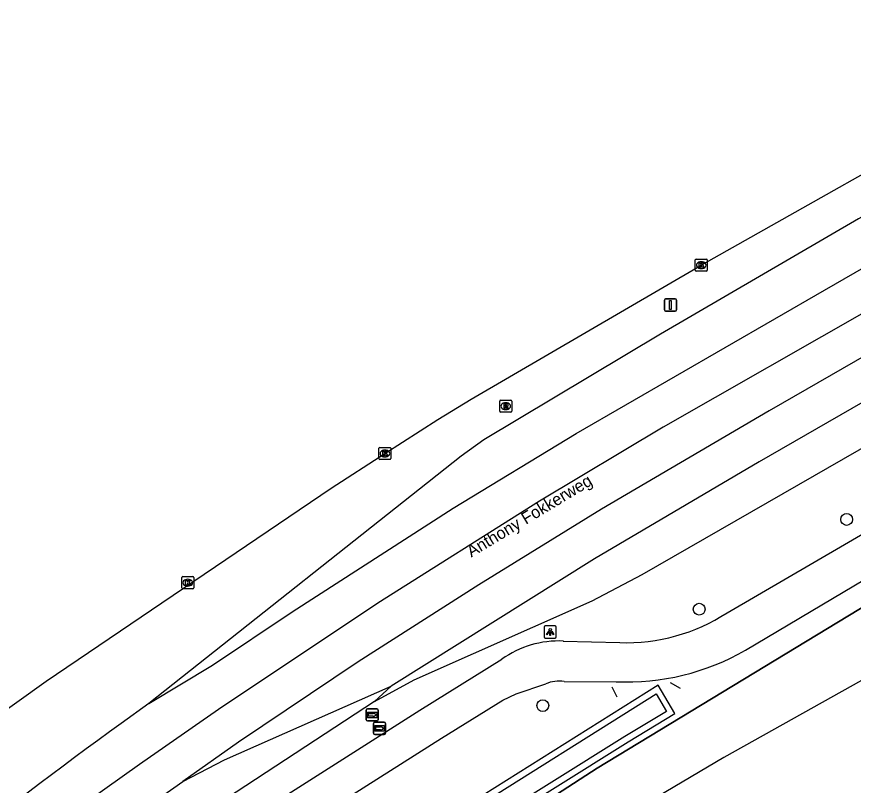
# Model space of a CAD drawing. Extents: x 156502 to 159074, y 384229 to 386094.
# Drawn here: x 157013.2 to 157082.5, y 386020 to 386083.6 of the extents above; entities that cross this region are included whole.
import ezdxf

# ---------------------------------------------------------------- set-up
doc = ezdxf.new("R2010")
doc.units = 0
for name, color, linetype in [('IMGEO_Boom', 7, 'Continuous'), ('IMGEO_Bouwland', 7, 'Continuous'), ('IMGEO_Fietspad_gesloten', 7, 'Continuous'), ('IMGEO_Groenvoorziening', 7, 'Continuous'), ('IMGEO_Hek', 7, 'Continuous'), ('IMGEO_Kolk', 7, 'Continuous'), ('IMGEO_Lichtpunt', 7, 'Continuous'), ('IMGEO_Openbare_ruimte_label', 7, 'Continuous'), ('IMGEO_OVBaan_gesloten', 7, 'Continuous'), ('IMGEO_Rijbaan_regionaal_gesloten', 7, 'Continuous'), ('IMGEO_Rioolput', 7, 'Continuous'), ('IMGEO_Verkeersbordpaal', 7, 'Continuous'), ('IMGEO_Waterloop', 7, 'Continuous'), ('IMGEO_Wegwijzer', 7, 'Continuous')]:
    doc.layers.add(name, color=color, linetype=linetype)

msp = doc.modelspace()

# ---------------------------------------------------------------- linework, layer by layer
at = {"layer": 'IMGEO_Boom'}
for centre in [(157081.974, 386042), (157069.759, 386034.566), (157056.805, 386026.582)]:
    msp.add_circle(centre, 0.489, dxfattribs=at)
at = {"layer": 'IMGEO_Bouwland'}
msp.add_lwpolyline([(157141.859, 386060.718), (157107.644, 386042.332), (157071.795, 386022.274), (157033.353, 385999.519), (156996.417, 385971.473), (156962.206, 385939.803), (156965.937, 385930.622), (156974.125, 385919.066)], dxfattribs=at)
at = {"layer": 'IMGEO_Fietspad_gesloten'}
for points in [[(157072.063, 386034.271), (157088.994, 386044.123), (157155.519, 386082.013), (157157.693, 386083.251)], [(157073.59, 386031.17), (157090.661, 386041.292), (157160.05, 386080.464), (157161.641, 386081.37)], [(157058.505, 386031.924), (157063.182, 386031.801)], [(156947.115, 385948.723), (156951.253, 385951.953), (156956.484, 385955.751), (156958.519, 385957.311), (156975.237, 385970.847), (156982.362, 385977.25), (156987.733, 385982.039), (156998.41, 385991.899), (157003.359, 385996.261), (157010.315, 386001.903), (157017.759, 386007.517), (157018.369, 386007.907), (157033.855, 386018.072), (157046.619, 386026.189), (157053.409, 386030.418)], [(156961.685, 385956.126), (156969.428, 385962.365), (156977.138, 385968.608), (156984.393, 385974.95), (156989.795, 385979.766), (157000.465, 385989.621), (157005.341, 385993.917), (157012.203, 385999.483), (157017.681, 386003.762), (157035.731, 386015.86), (157048.414, 386023.88), (157053.502, 386027.026), (157054.6, 386027.545), (157057.049, 386028.379)], [(157058.582, 386028.585), (157062.871, 386028.558)]]:
    msp.add_lwpolyline(points, dxfattribs=at)
for centre, radius, start, end in [((157063.744, 386046.982), 15.191, 267.88017, 303.20465), ((157058.125, 386023.836), 8.097, 87.30674, 125.62081), ((157063.749, 386048.255), 19.717, 267.44776, 299.94205), ((157058.181, 386025.765), 2.849, 81.90134, 113.40545)]:
    msp.add_arc(centre, radius, start, end, dxfattribs=at)
at = {"layer": 'IMGEO_Groenvoorziening'}
for points in [[(156954.711, 385939.318), (156962.504, 385946.935), (156973.181, 385956.868), (156983.37, 385965.891), (157000, 385979.428), (157009.209, 385986.533), (157018.541, 385993.367), (157028.46, 386000), (157035.37, 386004.621), (157061.311, 386021.393), (157085.574, 386036.103), (157115.223, 386052.978), (157120.284, 386055.801), (157152.797, 386073.936)], [(157051.792, 386016.01), (157063.869, 386023.588), (157067.751, 386025.926), (157066.365, 386028.267), (157049.937, 386017.943), (157033.804, 386007.371), (157022.366, 386000)]]:
    msp.add_lwpolyline(points, dxfattribs=at)
at = {"layer": 'IMGEO_Hek'}
for points in [[(157120.284, 386055.801), (157115.223, 386052.978), (157085.574, 386036.103), (157061.311, 386021.393), (157035.37, 386004.621), (157028.46, 386000)], [(157068.211, 386028), (157067.37, 386028.454)], [(157062.976, 386027.291), (157062.54, 386028.101)]]:
    msp.add_lwpolyline(points, dxfattribs=at)
at = {"layer": 'IMGEO_Kolk'}
for p, q in [((157069.504, 386063.564), (157070.356, 386063.564)), ((157069.429, 386062.638), (157069.429, 386063.49)), ((157069.917, 386063.344), (157069.942, 386063.344)), ((157070.43, 386063.49), (157070.43, 386062.638)), ((157070.356, 386062.564), (157069.504, 386062.564)), ((157069.94, 386062.784), (157069.915, 386062.784)), ((157043.222, 386047.038), (157043.222, 386047.89)), ((157043.297, 386047.964), (157044.149, 386047.964)), ((157043.71, 386047.744), (157043.735, 386047.744)), ((157044.223, 386047.89), (157044.223, 386047.038)), ((157044.149, 386046.964), (157043.297, 386046.964)), ((157043.733, 386047.184), (157043.708, 386047.184)), ((157026.899, 386036.334), (157026.899, 386037.186)), ((157026.974, 386037.26), (157027.826, 386037.26)), ((157027.9, 386037.186), (157027.9, 386036.334)), ((157027.387, 386037.04), (157027.412, 386037.04)), ((157027.826, 386036.26), (157026.974, 386036.26)), ((157027.41, 386036.48), (157027.385, 386036.48))]:
    msp.add_line(p, q, dxfattribs=at)
for points in [[(157069.504, 386063.564), (157070.356, 386063.564)], [(157069.429, 386062.638), (157069.429, 386063.49)], [(157069.75, 386063.264), (157069.873, 386063.264), (157069.873, 386063.113), (157070.003, 386063.264), (157070.167, 386063.264), (157070.021, 386063.113), (157070.174, 386062.864), (157070.022, 386062.864), (157069.937, 386063.028), (157069.873, 386062.961), (157069.873, 386062.864), (157069.75, 386062.864), (157069.75, 386063.264)], [(157070.43, 386063.49), (157070.43, 386062.638)], [(157070.356, 386062.564), (157069.504, 386062.564)], [(157043.222, 386047.038), (157043.222, 386047.89)], [(157043.297, 386047.964), (157044.149, 386047.964)], [(157043.543, 386047.664), (157043.666, 386047.664), (157043.666, 386047.513), (157043.796, 386047.664), (157043.96, 386047.664), (157043.814, 386047.513), (157043.967, 386047.264), (157043.815, 386047.264), (157043.73, 386047.428), (157043.666, 386047.361), (157043.666, 386047.264), (157043.543, 386047.264), (157043.543, 386047.664)], [(157044.223, 386047.89), (157044.223, 386047.038)], [(157044.149, 386046.964), (157043.297, 386046.964)], [(157026.899, 386036.334), (157026.899, 386037.186)], [(157026.974, 386037.26), (157027.826, 386037.26)], [(157027.9, 386037.186), (157027.9, 386036.334)], [(157027.22, 386036.96), (157027.343, 386036.96), (157027.343, 386036.809), (157027.473, 386036.96), (157027.637, 386036.96), (157027.491, 386036.809), (157027.644, 386036.56), (157027.492, 386036.56), (157027.407, 386036.724), (157027.343, 386036.657), (157027.343, 386036.56), (157027.22, 386036.56), (157027.22, 386036.96)], [(157027.826, 386036.26), (157026.974, 386036.26)]]:
    msp.add_lwpolyline(points, dxfattribs=at)
for centre, start, end in [((157069.506, 386063.488), 91.55205, 178.44795), ((157069.506, 386063.488), 91.55205, 178.44795), ((157070.354, 386063.488), 1.55205, 88.44795), ((157070.354, 386063.488), 1.55205, 88.44795), ((157069.506, 386062.64), 181.55205, 268.44795), ((157069.506, 386062.64), 181.55205, 268.44795), ((157070.354, 386062.64), 271.55205, 358.44795), ((157070.354, 386062.64), 271.55205, 358.44795), ((157043.299, 386047.888), 91.55205, 178.44795), ((157043.299, 386047.888), 91.55205, 178.44795), ((157044.147, 386047.888), 1.55205, 88.44795), ((157044.147, 386047.888), 1.55205, 88.44795), ((157043.299, 386047.04), 181.55205, 268.44795), ((157043.299, 386047.04), 181.55205, 268.44795), ((157044.147, 386047.04), 271.55205, 358.44795), ((157044.147, 386047.04), 271.55205, 358.44795), ((157026.976, 386037.184), 91.55205, 178.44795), ((157026.976, 386037.184), 91.55205, 178.44795), ((157027.824, 386037.184), 1.55205, 88.44795), ((157027.824, 386037.184), 1.55205, 88.44795), ((157026.976, 386036.336), 181.55205, 268.44795), ((157026.976, 386036.336), 181.55205, 268.44795), ((157027.824, 386036.336), 271.55205, 358.44795), ((157027.824, 386036.336), 271.55205, 358.44795)]:
    msp.add_arc(centre, 0.0765, start, end, dxfattribs=at)
for centre, major_axis, ratio, start_param, end_param in [((157069.916, 386063.064), (-0.387, 0.002), 0.722429, 4.712389, 7.853982), ((157069.941, 386063.064), (-0.39, 0.002), 0.717154, 1.570796, 4.712389), ((157043.709, 386047.464), (-0.387, 0.002), 0.722429, 4.712389, 7.853982), ((157043.734, 386047.464), (-0.39, 0.002), 0.717154, 1.570796, 4.712389), ((157027.386, 386036.76), (-0.387, 0.002), 0.722429, 4.712389, 7.853982), ((157027.411, 386036.76), (-0.39, 0.002), 0.717154, 1.570796, 4.712389)]:
    msp.add_ellipse(centre, major_axis=major_axis, ratio=ratio, start_param=start_param, end_param=end_param, dxfattribs=at)
at = {"layer": 'IMGEO_Lichtpunt'}
for p, q in [((157056.917, 386033.079), (157056.917, 386032.272)), ((157056.917, 386033.079), (157056.917, 386032.272)), ((157057.819, 386033.174), (157057.011, 386033.174)), ((157057.819, 386033.174), (157057.011, 386033.174)), ((157057.913, 386032.272), (157057.913, 386033.079)), ((157057.913, 386032.272), (157057.913, 386033.079)), ((157057.011, 386032.178), (157057.819, 386032.178)), ((157057.011, 386032.178), (157057.819, 386032.178))]:
    msp.add_line(p, q, dxfattribs=at)
for points in [[(157057.291, 386032.743), (157057.33, 386032.715), (157057.142, 386032.453), (157057.104, 386032.48), (157057.291, 386032.743)], [(157057.393, 386032.695), (157057.44, 386032.695), (157057.44, 386032.373), (157057.393, 386032.373), (157057.393, 386032.695)], [(157057.503, 386032.715), (157057.541, 386032.742), (157057.728, 386032.48), (157057.689, 386032.452), (157057.503, 386032.715)]]:
    msp.add_lwpolyline(points, dxfattribs=at)
msp.add_circle((157057.416, 386032.877), 0.0994, dxfattribs=at)
for centre, start, end in [((157057.011, 386033.079), 90, 180), ((157057.011, 386033.079), 90, 180), ((157057.819, 386033.079), 0, 90), ((157057.819, 386033.079), 0, 90), ((157057.011, 386032.272), 180, 270), ((157057.011, 386032.272), 180, 270), ((157057.819, 386032.272), 270, 0), ((157057.819, 386032.272), 270, 360)]:
    msp.add_arc(centre, 0.0946, start, end, dxfattribs=at)
at = {"layer": 'IMGEO_OVBaan_gesloten'}
for points in [[(157026.997, 386020.297), (157030.426, 386022.09), (157044.247, 386028.186)], [(157044.247, 386028.186), (157042.85, 386026.929)], [(157042.85, 386026.929), (157027.314, 386016.727), (157014.962, 386008.38), (157001.907, 385999.125), (157001.894, 385999.114)], [(156945.251, 385950.822), (156962.083, 385966.824), (156976.989, 385980.102), (156996.744, 385996.742), (157006.403, 386004.757), (157013.644, 386010.539), (157020.382, 386015.656), (157026.997, 386020.297)]]:
    msp.add_lwpolyline(points, dxfattribs=at)
at = {"layer": 'IMGEO_Rijbaan_regionaal_gesloten'}
for points in [[(157112.545, 386083.64), (157096.002, 386074.336), (157082.968, 386066.912), (157066.544, 386057.335), (157051.93, 386048.596), (157050.042, 386047.238), (157024.165, 386026.762)], [(157024.165, 386026.762), (157029.454, 386029.92), (157036.054, 386034.341), (157049.378, 386042.931), (157059.557, 386049.121), (157080.15, 386060.991), (157100.668, 386072.797), (157117.907, 386082.682)], [(157119.528, 386079.87), (157101.546, 386069.596), (157084.202, 386059.591), (157066.767, 386049.648), (157056.537, 386043.513), (157043.13, 386035.069), (157029.939, 386026.251), (157023.402, 386021.708), (157017.648, 386017.606), (157013.774, 386014.708), (157005.167, 386007.853), (156995.937, 386000.282), (156986.671, 385992.565), (156976.948, 385984.306), (156967.977, 385976.503), (156959.136, 385968.488), (156943.573, 385953.713)], [(157121.098, 386077.147), (157103.064, 386066.827), (157075.553, 386050.997), (157061.67, 386042.848), (157051.495, 386036.595), (157041.498, 386030.211), (157031.595, 386023.549), (157026.997, 386020.297)], [(156938.555, 385962.82), (156938.842, 385963.097), (156942.123, 385966.263), (156954.574, 385978.635), (156974.489, 385996.551), (156978.642, 386000), (156979.094, 386000.375), (156984.669, 386004.968), (156991.241, 386010.244), (157000, 386017.067), (157005.574, 386021.288), (157010.597, 386024.976), (157015.666, 386028.614), (157039.286, 386044.593), (157043.719, 386047.465), (157048.122, 386050.274), (157050.884, 386051.964), (157069.925, 386063.065), (157093.929, 386076.579)], [(157122.709, 386074.353), (157105.237, 386064.332), (157074.723, 386046.785), (157061.084, 386038.746), (157044.247, 386028.186)], [(157042.85, 386026.929), (157046.143, 386028.726), (157060.887, 386035.244), (157065.043, 386037.45), (157124.356, 386071.514)], [(157024.165, 386026.762), (157021.884, 386025.104)]]:
    msp.add_lwpolyline(points, dxfattribs=at)
msp.add_arc((157318.834, 385615.267), 506.108, 125.92546, 130.25673, dxfattribs=at)
at = {"layer": 'IMGEO_Rioolput'}
for p, q in [((157053.232, 386050.958), (157053.232, 386051.81)), ((157053.307, 386051.884), (157054.159, 386051.884)), ((157054.233, 386051.81), (157054.233, 386050.958)), ((157053.743, 386051.104), (157053.718, 386051.104)), ((157053.72, 386051.664), (157053.745, 386051.664)), ((157054.159, 386050.884), (157053.307, 386050.884))]:
    msp.add_line(p, q, dxfattribs=at)
for points in [[(157053.232, 386050.958), (157053.232, 386051.81)], [(157053.307, 386051.884), (157054.159, 386051.884)], [(157054.233, 386051.81), (157054.233, 386050.958)], [(157053.821, 386051.582), (157053.569, 386051.584), (157053.569, 386051.184)], [(157053.569, 386051.184), (157053.693, 386051.184), (157053.693, 386051.346), (157053.704, 386051.346)], [(157053.747, 386051.503), (157053.693, 386051.503), (157053.693, 386051.422)], [(157053.693, 386051.422), (157053.745, 386051.422)], [(157053.751, 386051.317), (157053.822, 386051.184), (157053.962, 386051.184), (157053.897, 386051.31)], [(157054.159, 386050.884), (157053.307, 386050.884)]]:
    msp.add_lwpolyline(points, dxfattribs=at)
for centre, radius, start, end in [((157053.309, 386051.808), 0.0765, 91.55205, 178.44795), ((157053.309, 386051.808), 0.0765, 91.55205, 178.44795), ((157054.157, 386051.808), 0.0765, 1.55205, 88.44795), ((157054.157, 386051.808), 0.0765, 1.55205, 88.44795), ((157053.703, 386051.293), 0.0533, 26.02933, 88.69889), ((157053.729, 386051.611), 0.19, 274.7715, 282.96867), ((157053.753, 386051.407), 0.0964, 77.00612, 93.18647), ((157053.767, 386051.464), 0.0378, 276.66336, 79.67722), ((157053.82, 386051.472), 0.109, 350.36119, 89.41601), ((157053.818, 386051.472), 0.112, 277.58423, 350.98172), ((157053.802, 386051.257), 0.108, 29.51342, 73.79051), ((157053.309, 386050.96), 0.0765, 181.55205, 268.44795), ((157053.309, 386050.96), 0.0765, 181.55205, 268.44795), ((157054.157, 386050.96), 0.0765, 271.55205, 358.44795), ((157054.157, 386050.96), 0.0765, 271.55205, 358.44795)]:
    msp.add_arc(centre, radius, start, end, dxfattribs=at)
for centre, major_axis, ratio, start_param, end_param in [((157053.719, 386051.384), (-0.387, 0.002), 0.722429, 4.712389, 7.853982), ((157053.744, 386051.384), (-0.39, 0.002), 0.717154, 1.570796, 4.712389)]:
    msp.add_ellipse(centre, major_axis=major_axis, ratio=ratio, start_param=start_param, end_param=end_param, dxfattribs=at)
at = {"layer": 'IMGEO_Verkeersbordpaal'}
for p, q in [((157066.88, 386059.363), (157066.88, 386060.163)), ((157066.88, 386060.163), (157066.88, 386059.363)), ((157066.98, 386060.263), (157067.77, 386060.263)), ((157067.77, 386060.263), (157066.98, 386060.263)), ((157067.87, 386060.163), (157067.87, 386059.363)), ((157067.87, 386059.363), (157067.87, 386060.163)), ((157067.77, 386059.263), (157066.98, 386059.263)), ((157066.98, 386059.263), (157067.77, 386059.263))]:
    msp.add_line(p, q, dxfattribs=at)
msp.add_lwpolyline([(157067.3, 386060.138), (157067.45, 386060.138), (157067.45, 386059.388), (157067.3, 386059.388), (157067.3, 386060.138)], dxfattribs=at)
for centre, start, end in [((157066.98, 386060.163), 90, 180), ((157066.98, 386060.163), 90, 180), ((157067.77, 386060.163), 0, 90), ((157067.77, 386060.163), 360, 90), ((157066.98, 386059.363), 180, 270), ((157066.98, 386059.363), 180, 270), ((157067.77, 386059.363), 270, 0), ((157067.77, 386059.363), 270, 0)]:
    msp.add_arc(centre, 0.1, start, end, dxfattribs=at)
at = {"layer": 'IMGEO_Waterloop'}
msp.add_lwpolyline([(157004.238, 385986.74), (157010.31, 385991.108), (157016.448, 385995.384), (157022.648, 385999.568), (157034.085, 386006.939), (157050.216, 386017.509), (157066.191, 386027.549), (157067.047, 386026.104), (157063.599, 386024.027), (157051.514, 386016.444), (157034.076, 386005.07), (157026.908, 386000.431), (157019.656, 385995.489), (157012.526, 385990.373), (157005.521, 385985.086), (157004.238, 385986.74)], dxfattribs=at)
at = {"layer": 'IMGEO_Wegwijzer'}
for p, q in [((157042.179, 386025.407), (157042.179, 386026.207)), ((157042.179, 386026.207), (157042.179, 386025.407)), ((157042.279, 386026.307), (157043.069, 386026.307)), ((157043.069, 386026.307), (157042.279, 386026.307)), ((157043.169, 386026.207), (157043.169, 386025.407)), ((157043.169, 386025.407), (157043.169, 386026.207)), ((157043.069, 386025.307), (157042.279, 386025.307)), ((157042.279, 386025.307), (157043.069, 386025.307)), ((157042.786, 386024.296), (157042.786, 386025.096)), ((157042.786, 386025.096), (157042.786, 386024.296)), ((157042.886, 386025.196), (157043.676, 386025.196)), ((157043.676, 386025.196), (157042.886, 386025.196)), ((157043.776, 386025.096), (157043.776, 386024.296)), ((157043.776, 386024.296), (157043.776, 386025.096)), ((157043.676, 386024.196), (157042.886, 386024.196)), ((157042.886, 386024.196), (157043.676, 386024.196))]:
    msp.add_line(p, q, dxfattribs=at)
for points in [[(157042.28, 386026.039), (157043.068, 386026.039), (157043.068, 386025.575), (157042.28, 386025.575), (157042.28, 386026.039)], [(157042.345, 386025.891), (157042.345, 386025.807), (157042.345, 386025.723), (157042.756, 386025.723), (157042.756, 386025.64), (157043.003, 386025.807), (157042.756, 386025.974), (157042.756, 386025.891), (157042.345, 386025.891)], [(157042.887, 386024.928), (157043.675, 386024.928), (157043.675, 386024.464), (157042.887, 386024.464), (157042.887, 386024.928)], [(157042.952, 386024.78), (157042.952, 386024.696), (157042.952, 386024.612), (157043.363, 386024.612), (157043.363, 386024.529), (157043.61, 386024.696), (157043.363, 386024.863), (157043.363, 386024.78), (157042.952, 386024.78)]]:
    msp.add_lwpolyline(points, dxfattribs=at)
for centre, start, end in [((157042.279, 386026.207), 90, 180), ((157042.279, 386026.207), 90, 180), ((157043.069, 386026.207), 0, 90), ((157043.069, 386026.207), 360, 90), ((157042.279, 386025.407), 180, 270), ((157042.279, 386025.407), 180, 270), ((157043.069, 386025.407), 270, 0), ((157043.069, 386025.407), 270, 0), ((157042.886, 386025.096), 90, 180), ((157042.886, 386025.096), 90, 180), ((157043.676, 386025.096), 0, 90), ((157043.676, 386025.096), 360, 90), ((157042.886, 386024.296), 180, 270), ((157042.886, 386024.296), 180, 270), ((157043.676, 386024.296), 270, 0), ((157043.676, 386024.296), 270, 0)]:
    msp.add_arc(centre, 0.1, start, end, dxfattribs=at)

# ---------------------------------------------------------------- texts
at = {"layer": 'IMGEO_Openbare_ruimte_label'}
msp.add_text('Anthony Fokkerweg', height=1, rotation=31.05216, dxfattribs=at).set_placement((157050.88, 386038.831))

doc.saveas('drawing.dxf')
